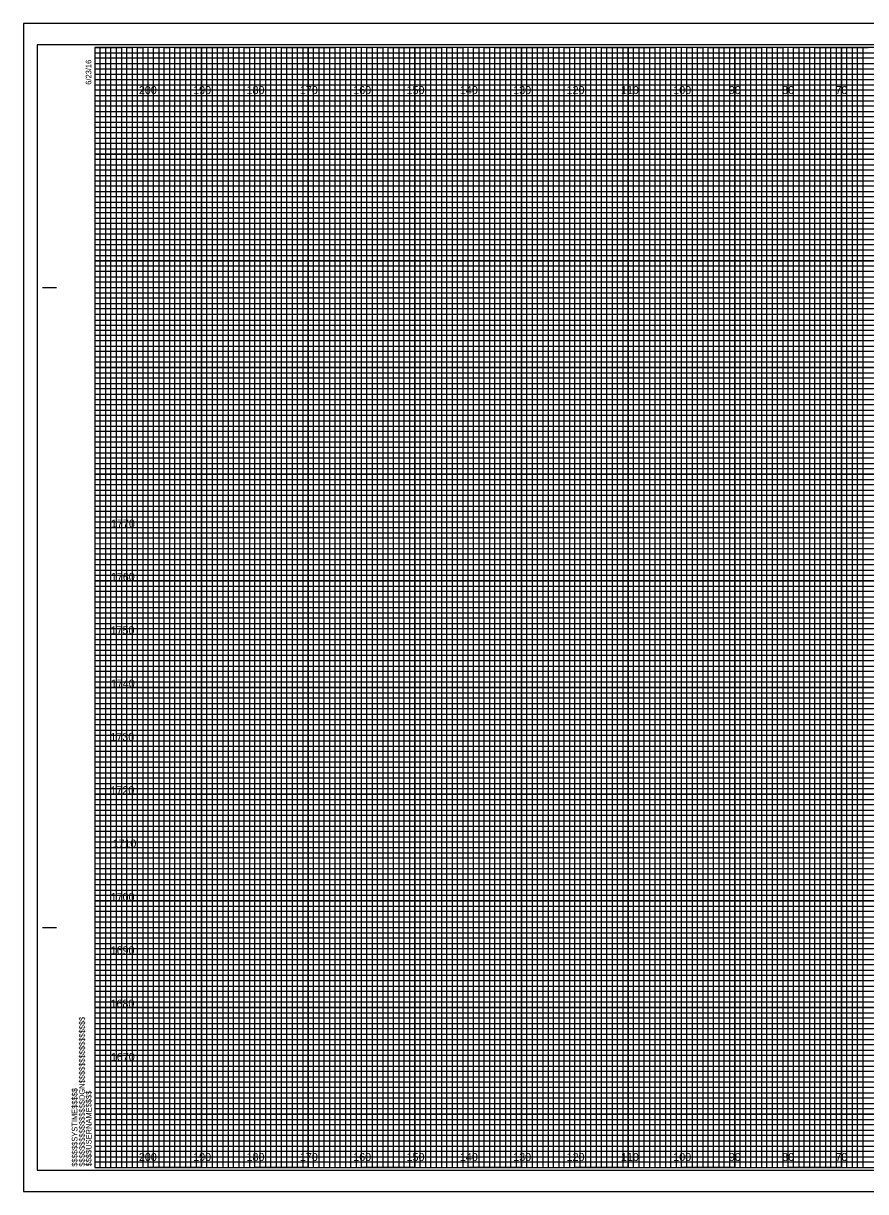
# Model space of a CAD drawing. Extents: x -419 to 4739, y -630 to 13534.
# Drawn here: x 2640.9 to 2798.8, y 194.1 to 413.1 of the extents above; entities that cross this region are included whole.
import ezdxf

# ---------------------------------------------------------------- set-up
doc = ezdxf.new("R2010")
doc.units = 0
for name, color, linetype in [('Old_Level_62', 7, 'Continuous'), ('Pattern 1', 7, 'Continuous'), ('Pattern 18', 7, 'Continuous'), ('Pattern 4', 7, 'Continuous'), ('Pattern 5', 7, 'Continuous'), ('Prop Dimension', 7, 'Continuous'), ('Prop Horizontal Alignment', 7, 'Continuous'), ('Raster_Level_0', 7, 'Continuous'), ('Scratch_Level_0', 7, 'Continuous'), ('Scratch_Level_3', 7, 'Continuous'), ('Scratch_Level_5', 7, 'Continuous')]:
    doc.layers.add(name, color=color, linetype=linetype)

msp = doc.modelspace()

# ---------------------------------------------------------------- linework, layer by layer
at = {"layer": 'Old_Level_62'}
for p, q in [((2644.45, 363.59), (2646.95, 363.59)), ((2644.55, 363.59), (2647.05, 363.59)), ((2644.45, 243.59), (2646.95, 243.59)), ((2644.55, 243.59), (2647.05, 243.59)), ((2654.25, 198.59), (2654.25, 198.59)), ((2654.25, 198.59), (2654.25, 198.59)), ((2654.25, 198.59), (2654.25, 198.59)), ((2654.25, 198.59), (2654.25, 198.59)), ((2654.25, 198.59), (2654.25, 198.59)), ((2654.25, 198.59), (2654.25, 198.59)), ((2654.25, 198.59), (2654.25, 198.59))]:
    msp.add_line(p, q, dxfattribs=at)
msp.add_lwpolyline([(2974.25, 408.59), (2654.25, 408.59), (2654.25, 198.59), (2974.25, 198.59)], close=True, dxfattribs=at)
at = {"layer": 'Pattern 18'}
msp.add_lwpolyline([(2640.85, 194.09), (2977.55, 194.09), (2977.55, 413.09), (2640.85, 413.09)], close=True, dxfattribs=at)
at = {"layer": 'Pattern 4'}
for p, q in [((2654.25, 407.59), (2914.25, 407.59)), ((2914.25, 406.57), (2654.25, 406.57)), ((2654.25, 406.57), (2654.25, 405.59)), ((2654.25, 405.59), (2914.25, 405.59)), ((2914.25, 404.48), (2654.25, 404.48)), ((2654.25, 404.48), (2654.25, 402.59)), ((2654.25, 402.59), (2974.25, 402.59))]:
    msp.add_line(p, q, dxfattribs=at)
for points in [[(2654.25, 401.59), (2924.25, 401.59), (2974.25, 401.59), (2974.25, 400.59), (2654.25, 400.59)], [(2654.25, 399.59), (2974.25, 399.59), (2974.25, 397.59), (2654.25, 397.59)], [(2654.25, 396.59), (2974.25, 396.59), (2974.25, 395.59), (2654.25, 395.57)], [(2654.25, 394.59), (2974.25, 394.59), (2974.25, 392.59), (2654.25, 392.59)], [(2654.25, 391.59), (2974.25, 391.59), (2974.25, 390.59), (2654.25, 390.59)], [(2654.25, 389.59), (2974.25, 389.59), (2974.25, 387.59), (2654.25, 387.59)], [(2654.25, 386.59), (2974.25, 386.59), (2974.25, 385.59), (2654.25, 385.59)], [(2654.25, 384.59), (2974.25, 384.59), (2974.25, 382.59), (2654.25, 382.59)], [(2654.25, 381.59), (2974.25, 381.59), (2974.25, 380.59), (2654.25, 380.59)], [(2654.25, 379.59), (2974.25, 379.59), (2974.25, 377.59), (2654.25, 377.59)], [(2654.25, 376.59), (2974.25, 376.59), (2974.25, 375.59), (2654.25, 375.59)], [(2654.25, 374.59), (2974.25, 374.59), (2974.25, 372.54), (2974.25, 371.59), (2974.25, 370.59), (2654.25, 370.59)], [(2654.25, 372.59), (2974.25, 372.59), (2974.25, 371.59), (2654.25, 371.59)], [(2654.25, 369.59), (2974.25, 369.59), (2974.25, 367.59), (2654.25, 367.62)], [(2654.25, 367.62), (2974.25, 367.59), (2974.25, 366.59), (2654.25, 366.59)], [(2654.25, 365.59), (2974.25, 365.59), (2974.25, 364.59), (2654.25, 364.59)], [(2654.25, 362.59), (2974.25, 362.59), (2974.25, 361.59), (2654.25, 361.59)], [(2654.25, 360.59), (2974.25, 360.59), (2974.25, 359.59), (2654.25, 359.59)], [(2654.18, 357.48), (2974.25, 357.48), (2974.25, 356.47), (2654.18, 356.47)], [(2654.25, 355.59), (2974.25, 355.59), (2974.25, 354.59), (2654.25, 354.59)], [(2654.25, 352.59), (2974.25, 352.59), (2974.25, 351.59), (2654.25, 351.59)], [(2654.25, 350.59), (2974.25, 350.59), (2974.25, 349.59), (2654.25, 349.59)], [(2654.25, 347.59), (2974.25, 347.59), (2974.25, 346.59), (2654.25, 346.59)], [(2654.25, 345.59), (2974.25, 345.59), (2974.25, 344.59), (2654.25, 344.59)], [(2654.25, 342.59), (2974.25, 342.59), (2974.25, 341.59), (2654.25, 341.59)], [(2654.25, 340.59), (2974.25, 340.59), (2974.25, 339.59), (2654.25, 339.59)], [(2654.25, 337.59), (2974.25, 337.59), (2974.24, 336.57), (2654.25, 336.59)], [(2654.25, 335.59), (2974.25, 335.59), (2974.25, 334.59), (2654.25, 334.59)], [(2654.25, 332.59), (2974.25, 332.59), (2974.25, 331.59), (2654.25, 331.59)], [(2654.25, 330.59), (2974.25, 330.59), (2974.25, 329.59), (2654.25, 329.59)], [(2654.25, 327.59), (2974.25, 327.59), (2974.25, 326.59), (2654.25, 326.59)], [(2654.25, 325.59), (2974.25, 325.59), (2974.25, 324.59), (2654.25, 324.59)], [(2654.25, 322.59), (2974.25, 322.59), (2974.25, 321.59), (2654.25, 321.59)], [(2654.25, 320.59), (2974.25, 320.59), (2974.25, 319.59), (2654.25, 319.59)], [(2654.25, 317.59), (2974.25, 317.59), (2974.25, 316.59), (2654.25, 316.59)], [(2654.25, 315.58), (2974.32, 315.5), (2974.25, 314.59), (2654.25, 314.59)], [(2654.25, 312.59), (2974.25, 312.59), (2974.25, 311.59), (2654.25, 311.59)], [(2654.25, 310.59), (2974.25, 310.59), (2974.25, 309.59), (2654.25, 309.59)], [(2654.25, 307.59), (2974.25, 307.59), (2974.25, 306.59), (2654.25, 306.59)], [(2654.25, 305.59), (2974.25, 305.59), (2974.25, 304.59), (2654.25, 304.59)], [(2654.25, 302.59), (2974.25, 302.59), (2974.25, 301.59), (2654.25, 301.59)], [(2654.25, 300.59), (2974.25, 300.59), (2974.25, 299.59), (2654.25, 299.59)], [(2654.25, 297.59), (2974.25, 297.59), (2974.25, 296.59), (2654.25, 296.59)], [(2654.25, 295.59), (2974.25, 295.59), (2974.25, 294.59), (2654.25, 294.59)], [(2654.25, 292.59), (2974.25, 292.59), (2974.25, 291.59), (2654.25, 291.59)], [(2654.25, 290.59), (2974.25, 290.59), (2974.25, 289.59), (2654.25, 289.59)], [(2654.25, 287.59), (2974.25, 287.59), (2974.25, 286.59), (2654.25, 286.59)], [(2654.25, 285.59), (2974.25, 285.59), (2974.25, 284.59), (2654.25, 284.59)], [(2654.25, 282.59), (2974.25, 282.59), (2974.25, 281.59), (2654.25, 281.59)], [(2654.25, 280.59), (2974.25, 280.59), (2974.25, 279.59), (2654.25, 279.59)], [(2654.25, 277.59), (2974.25, 277.59), (2974.24, 276.57), (2654.25, 276.59)], [(2654.25, 275.59), (2974.25, 275.59), (2974.25, 274.59), (2654.25, 274.59)], [(2654.25, 272.59), (2974.25, 272.59), (2974.25, 271.59), (2654.25, 271.59)], [(2654.25, 270.59), (2974.25, 270.59), (2974.25, 269.59), (2654.25, 269.59)], [(2654.25, 267.59), (2974.25, 267.59), (2974.25, 266.59), (2654.25, 266.59)], [(2654.25, 265.59), (2974.25, 265.59), (2974.25, 264.59), (2654.25, 264.59)], [(2654.25, 262.59), (2974.25, 262.59), (2974.25, 261.59), (2654.25, 261.59)], [(2654.25, 260.59), (2974.25, 260.59), (2974.25, 259.59), (2654.25, 259.59)], [(2654.25, 257.59), (2974.25, 257.59), (2974.25, 256.59), (2654.25, 256.59)], [(2654.25, 255.58), (2974.32, 255.5), (2974.25, 254.59), (2654.25, 254.59)], [(2654.25, 252.59), (2974.25, 252.59), (2974.25, 251.59), (2654.25, 251.59)], [(2654.25, 250.59), (2974.25, 250.59), (2974.25, 249.59), (2654.25, 249.59)], [(2654.25, 247.59), (2974.25, 247.59), (2974.25, 246.59), (2654.25, 246.59)], [(2654.25, 245.59), (2974.25, 245.59), (2974.25, 244.59), (2654.25, 244.59)], [(2654.25, 242.59), (2974.25, 242.59), (2974.25, 241.59), (2654.25, 241.59)], [(2654.25, 240.59), (2974.25, 240.59), (2974.25, 239.59), (2654.25, 239.59)], [(2654.25, 237.59), (2974.25, 237.59), (2974.25, 236.59), (2654.25, 236.59)], [(2654.25, 235.59), (2974.25, 235.59), (2974.25, 234.59), (2654.25, 234.59)], [(2654.25, 232.59), (2974.25, 232.59), (2974.25, 231.59), (2654.25, 231.59)], [(2654.25, 230.59), (2974.25, 230.59), (2974.25, 229.59), (2654.25, 229.59)], [(2654.25, 227.59), (2974.25, 227.59), (2974.25, 226.59), (2654.25, 226.59)], [(2654.25, 225.59), (2974.25, 225.59), (2974.25, 224.59), (2654.25, 224.59)], [(2654.25, 222.59), (2974.25, 222.59), (2974.25, 221.59), (2654.25, 221.59)], [(2654.25, 220.59), (2974.25, 220.59), (2974.25, 219.59), (2654.25, 219.59)], [(2654.25, 217.59), (2974.25, 217.59), (2974.25, 216.59), (2654.25, 216.59)], [(2654.25, 215.59), (2974.25, 215.59), (2974.25, 214.59), (2654.25, 214.59)], [(2654.25, 212.59), (2974.25, 212.59), (2974.25, 211.59), (2654.25, 211.59)], [(2654.25, 210.59), (2974.25, 210.59), (2974.25, 209.59), (2654.25, 209.59)], [(2654.25, 207.59), (2974.25, 207.59), (2974.25, 206.59), (2654.25, 206.59)], [(2654.25, 205.59), (2974.25, 205.59), (2974.25, 204.59), (2654.25, 204.59)], [(2654.25, 202.59), (2974.25, 202.59), (2974.25, 201.59), (2654.25, 201.59)], [(2654.25, 200.59), (2974.25, 200.59), (2974.25, 199.59), (2654.25, 199.59)]]:
    msp.add_lwpolyline(points, dxfattribs=at)
at = {"layer": 'Pattern 5'}
for p, q in [((2977.55, 413.09), (2640.85, 413.09)), ((2640.85, 413.09), (2640.85, 194.09)), ((2640.85, 194.09), (2977.55, 194.09))]:
    msp.add_line(p, q, dxfattribs=at)
at = {"layer": 'Prop Dimension'}
for points in [[(2654.25, 198.59), (2655.25, 198.59), (2655.25, 408.59), (2656.25, 408.59), (2656.25, 198.59)], [(2656.25, 198.59), (2657.25, 198.59), (2657.25, 408.59), (2658.25, 408.59), (2658.25, 198.59)], [(2659.25, 198.59), (2660.25, 198.59), (2660.25, 408.59), (2661.25, 408.59), (2661.25, 198.59)], [(2661.25, 198.59), (2662.25, 198.59), (2662.25, 408.59), (2663.25, 408.59), (2663.25, 198.59)], [(2664.25, 198.59), (2665.25, 198.59), (2665.25, 408.59), (2666.25, 408.59), (2666.25, 198.59)], [(2666.25, 198.59), (2667.25, 198.59), (2667.25, 408.59), (2668.25, 408.59), (2668.25, 198.59)], [(2669.25, 198.59), (2670.25, 198.59), (2670.25, 408.59), (2671.25, 408.59), (2671.25, 198.59)], [(2671.25, 198.59), (2672.25, 198.59), (2672.25, 408.59), (2673.25, 408.59), (2673.25, 198.59)], [(2674.25, 198.59), (2675.25, 198.59), (2675.25, 408.59), (2676.25, 408.59), (2676.25, 198.59)], [(2676.25, 198.59), (2677.25, 198.59), (2677.25, 408.59), (2678.25, 408.59), (2678.25, 198.59)], [(2679.25, 198.59), (2680.25, 198.59), (2680.25, 408.59), (2681.25, 408.59), (2681.25, 198.59)], [(2681.25, 198.59), (2682.25, 198.59), (2682.25, 408.59), (2683.25, 408.59), (2683.25, 198.59)], [(2684.25, 198.59), (2685.25, 198.59), (2685.25, 408.59), (2686.25, 408.59), (2686.25, 198.59)], [(2686.25, 198.59), (2687.25, 198.59), (2687.25, 408.59), (2688.25, 408.59), (2688.25, 198.59)], [(2689.25, 198.59), (2690.25, 198.59), (2690.25, 408.59), (2691.25, 408.59), (2691.25, 198.59)], [(2691.25, 198.59), (2692.25, 198.59), (2692.25, 408.59), (2693.25, 408.59), (2693.25, 198.59)], [(2694.25, 198.59), (2695.25, 198.59), (2695.25, 408.59), (2696.25, 408.59), (2696.25, 198.59)], [(2696.25, 198.59), (2697.25, 198.59), (2697.25, 408.59), (2698.25, 408.59), (2698.25, 198.59)], [(2699.25, 198.59), (2700.25, 198.59), (2700.25, 408.59), (2701.25, 408.59), (2701.25, 198.59)], [(2701.25, 198.59), (2702.25, 198.59), (2702.25, 408.59), (2703.25, 408.59), (2703.25, 198.59)], [(2704.25, 198.59), (2705.25, 198.59), (2705.25, 408.59), (2706.25, 408.59), (2706.25, 198.59)], [(2706.25, 198.59), (2707.25, 198.59), (2707.25, 408.59), (2708.25, 408.59), (2708.25, 198.59)], [(2709.25, 198.59), (2710.25, 198.59), (2710.25, 408.59), (2711.25, 408.59), (2711.25, 198.59)], [(2711.25, 198.59), (2712.25, 198.59), (2712.25, 408.59), (2713.25, 408.59), (2713.25, 198.59)], [(2714.25, 198.59), (2715.25, 198.59), (2715.25, 408.59), (2716.25, 408.59), (2716.25, 198.59)], [(2716.25, 198.59), (2717.25, 198.59), (2717.25, 408.59), (2718.25, 408.59), (2718.25, 198.59)], [(2719.25, 198.59), (2720.25, 198.59), (2720.25, 408.59), (2721.25, 408.59), (2721.25, 198.59)], [(2721.25, 198.59), (2722.25, 198.59), (2722.25, 408.59), (2723.25, 408.59), (2723.25, 198.59)], [(2724.25, 198.59), (2725.25, 198.59), (2725.25, 408.59), (2726.25, 408.59), (2726.25, 198.59)], [(2726.25, 198.59), (2727.25, 198.59), (2727.25, 408.59), (2728.25, 408.59), (2728.25, 198.59)], [(2729.25, 198.59), (2730.25, 198.59), (2730.25, 408.59), (2731.25, 408.59), (2731.25, 198.59)], [(2731.25, 198.59), (2732.25, 198.59), (2732.25, 408.59), (2733.25, 408.59), (2733.25, 198.59)], [(2734.25, 198.59), (2735.25, 198.59), (2735.25, 408.59), (2736.25, 408.59), (2736.25, 198.59)], [(2736.25, 198.59), (2737.25, 198.59), (2737.25, 408.59), (2738.25, 408.59), (2738.25, 198.59)], [(2739.25, 198.59), (2740.25, 198.59), (2740.25, 408.59), (2741.25, 408.59), (2741.25, 198.59)], [(2741.25, 198.59), (2742.25, 198.59), (2742.25, 408.59), (2743.25, 408.59), (2743.25, 198.59)], [(2744.25, 198.59), (2745.25, 198.59), (2745.25, 408.59), (2746.25, 408.59), (2746.25, 198.59)], [(2746.25, 198.59), (2747.25, 198.59), (2747.25, 408.59), (2748.25, 408.59), (2748.25, 198.59)], [(2749.25, 198.59), (2750.25, 198.59), (2750.25, 408.59), (2751.25, 408.59), (2751.25, 198.59)], [(2751.25, 198.59), (2752.25, 198.59), (2752.25, 408.59), (2753.25, 408.59), (2753.25, 198.59)], [(2754.25, 198.59), (2755.25, 198.59), (2755.25, 408.59), (2756.25, 408.59), (2756.25, 198.59)], [(2756.25, 198.59), (2757.25, 198.59), (2757.25, 408.59), (2758.25, 408.59), (2758.25, 198.59)], [(2759.25, 198.59), (2760.25, 198.59), (2760.25, 408.59), (2761.25, 408.59), (2761.25, 198.59)], [(2761.25, 198.59), (2762.25, 198.59), (2762.25, 408.59), (2763.25, 408.59), (2763.25, 198.59)], [(2764.25, 198.59), (2765.25, 198.59), (2765.25, 408.59), (2766.25, 408.59), (2766.25, 198.59)], [(2766.25, 198.59), (2767.25, 198.59), (2767.25, 408.59), (2768.25, 408.59), (2768.25, 198.59)], [(2769.25, 198.59), (2770.25, 198.59), (2770.25, 408.59), (2771.25, 408.59), (2771.25, 198.59)], [(2771.25, 198.59), (2772.25, 198.59), (2772.25, 408.59), (2773.25, 408.59), (2773.25, 198.59)], [(2774.25, 198.59), (2775.25, 198.59), (2775.25, 408.59), (2776.25, 408.59), (2776.25, 198.59)], [(2776.25, 198.59), (2777.25, 198.59), (2777.25, 408.59), (2778.25, 408.59), (2778.25, 198.59)], [(2779.25, 198.59), (2780.25, 198.59), (2780.25, 408.59), (2781.25, 408.59), (2781.25, 198.59)], [(2781.25, 198.59), (2782.25, 198.59), (2782.25, 408.59), (2783.25, 408.59), (2783.25, 198.59)], [(2784.25, 198.59), (2785.25, 198.59), (2785.25, 408.59), (2786.25, 408.59), (2786.25, 198.59)], [(2786.25, 198.59), (2787.25, 198.59), (2787.25, 408.59), (2788.25, 408.59), (2788.25, 198.59)], [(2789.25, 198.59), (2790.25, 198.59), (2790.25, 408.59), (2791.25, 408.59), (2791.25, 198.59)], [(2791.25, 198.59), (2792.25, 198.59), (2792.25, 408.59), (2793.25, 408.59), (2793.25, 198.59)], [(2794.25, 198.59), (2795.25, 198.59), (2795.25, 408.59), (2796.25, 408.59), (2796.25, 198.59)], [(2796.25, 198.59), (2797.25, 198.59), (2797.25, 408.59), (2798.25, 408.59), (2798.25, 198.59)]]:
    msp.add_lwpolyline(points, dxfattribs=at)
at = {"layer": 'Prop Horizontal Alignment'}
for points in [[(2654.25, 408.59), (2659.25, 408.59), (2659.25, 198.59), (2669.25, 198.59), (2669.25, 408.59), (2679.25, 408.59), (2679.25, 198.59), (2689.25, 198.59), (2689.25, 408.59), (2699.25, 408.59), (2699.25, 198.59), (2709.25, 198.59), (2709.25, 408.59), (2719.25, 408.59), (2719.25, 198.59), (2729.25, 198.59), (2729.25, 408.59), (2739.25, 408.59), (2739.25, 198.59), (2749.25, 198.59), (2749.25, 408.59), (2759.25, 408.59), (2759.25, 198.59), (2769.25, 198.59), (2769.25, 408.59), (2779.25, 408.59), (2779.25, 198.59), (2789.25, 198.59), (2789.25, 408.59), (2799.25, 408.59)], [(2654.25, 403.59), (2929.25, 403.59)], [(2654.25, 383.59), (2974.25, 383.59), (2974.25, 393.59), (2654.25, 393.59)], [(2654.25, 363.59), (2974.25, 363.59), (2974.25, 373.59), (2654.25, 373.59)], [(2654.25, 343.59), (2974.25, 343.59), (2974.25, 353.59), (2654.25, 353.59)], [(2654.25, 323.59), (2974.25, 323.59), (2974.25, 333.59), (2654.25, 333.59)], [(2654.25, 303.59), (2974.25, 303.59), (2974.25, 313.59), (2654.25, 313.59)], [(2654.25, 283.59), (2974.25, 283.59), (2974.25, 293.59), (2654.25, 293.59)], [(2654.25, 263.59), (2974.25, 263.59), (2974.25, 273.59), (2654.25, 273.59)], [(2654.25, 243.59), (2974.25, 243.59), (2974.25, 253.59), (2654.25, 253.59)], [(2654.25, 223.59), (2974.25, 223.59), (2974.25, 233.59), (2654.25, 233.59)], [(2654.25, 203.59), (2974.25, 203.59), (2974.25, 213.59), (2654.25, 213.59)]]:
    msp.add_lwpolyline(points, dxfattribs=at)
at = {"layer": 'Scratch_Level_0'}
for p, q in [((2664.25, 198.59), (2664.25, 408.59)), ((2674.25, 198.59), (2674.25, 408.59)), ((2684.25, 198.59), (2684.25, 408.59)), ((2694.25, 198.59), (2694.25, 408.59)), ((2704.25, 198.59), (2704.25, 408.59)), ((2714.25, 198.59), (2714.25, 408.59)), ((2724.25, 198.59), (2724.25, 408.59)), ((2734.25, 198.59), (2734.25, 408.59)), ((2744.25, 198.59), (2744.25, 408.59)), ((2754.25, 198.59), (2754.25, 408.59)), ((2764.25, 198.59), (2764.25, 408.59)), ((2774.25, 198.59), (2774.25, 408.59)), ((2784.25, 198.59), (2784.25, 408.59)), ((2794.25, 198.59), (2794.25, 408.59)), ((2654.25, 398.59), (2974.25, 398.59)), ((2654.25, 388.59), (2974.25, 388.59)), ((2654.25, 378.59), (2974.25, 378.59)), ((2654.25, 368.59), (2974.25, 368.59)), ((2654.25, 358.59), (2974.25, 358.59)), ((2654.25, 348.59), (2974.25, 348.59)), ((2654.25, 338.59), (2974.25, 338.59)), ((2654.25, 328.59), (2974.25, 328.59)), ((2654.25, 318.59), (2974.25, 318.59)), ((2654.25, 308.59), (2974.25, 308.59)), ((2654.25, 298.59), (2974.25, 298.59)), ((2654.25, 288.59), (2974.25, 288.59)), ((2654.25, 278.59), (2974.25, 278.59)), ((2654.25, 268.59), (2974.25, 268.59)), ((2654.25, 258.59), (2974.25, 258.59)), ((2654.25, 248.59), (2974.25, 248.59)), ((2654.25, 238.59), (2974.25, 238.59)), ((2654.25, 228.59), (2974.25, 228.59)), ((2654.25, 218.59), (2974.25, 218.59)), ((2654.25, 208.59), (2974.25, 208.59))]:
    msp.add_line(p, q, dxfattribs=at)
at = {"layer": 'Scratch_Level_3'}
for p, q in [((2664.25, 408.59), (2654.25, 408.59)), ((2664.25, 198.59), (2664.25, 408.59)), ((2684.25, 408.59), (2674.25, 408.59)), ((2674.25, 408.59), (2674.25, 198.59)), ((2684.25, 198.59), (2684.25, 408.59)), ((2704.25, 408.59), (2694.25, 408.59)), ((2694.25, 408.59), (2694.25, 198.59)), ((2704.25, 198.59), (2704.25, 408.59)), ((2724.25, 408.59), (2714.25, 408.59)), ((2714.25, 408.59), (2714.25, 198.59)), ((2724.25, 198.59), (2724.25, 408.59)), ((2744.25, 408.59), (2734.25, 408.59)), ((2734.25, 408.59), (2734.25, 198.59)), ((2744.25, 198.59), (2744.25, 408.59)), ((2764.25, 408.59), (2754.25, 408.59)), ((2754.25, 408.59), (2754.25, 198.59)), ((2764.25, 198.59), (2764.25, 408.59)), ((2784.25, 408.59), (2774.25, 408.59)), ((2774.25, 408.59), (2774.25, 198.59)), ((2784.25, 198.59), (2784.25, 408.59)), ((2804.25, 408.59), (2794.25, 408.59)), ((2794.25, 408.59), (2794.25, 198.59)), ((2674.25, 198.59), (2664.25, 198.59)), ((2694.25, 198.59), (2684.25, 198.59)), ((2714.25, 198.59), (2704.25, 198.59)), ((2734.25, 198.59), (2724.25, 198.59)), ((2754.25, 198.59), (2744.25, 198.59)), ((2774.25, 198.59), (2764.25, 198.59)), ((2794.25, 198.59), (2784.25, 198.59))]:
    msp.add_line(p, q, dxfattribs=at)
for points in [[(2654.25, 398.59), (2974.25, 398.59), (2974.25, 388.59), (2654.25, 388.59)], [(2654.25, 378.59), (2974.25, 378.59), (2974.25, 368.59), (2654.25, 368.59)], [(2654.25, 358.59), (2974.25, 358.59), (2974.25, 348.59), (2654.25, 348.59)], [(2654.25, 338.59), (2974.25, 338.59), (2974.25, 328.59), (2654.25, 328.59)], [(2654.25, 318.59), (2974.25, 318.59), (2974.25, 308.59), (2654.25, 308.59)], [(2654.25, 298.59), (2974.25, 298.59), (2974.25, 288.59), (2654.25, 288.59)], [(2654.25, 278.59), (2974.25, 278.59), (2974.25, 268.59), (2654.25, 268.59)], [(2654.25, 258.59), (2974.25, 258.59), (2974.25, 248.59), (2654.25, 248.59)], [(2654.25, 238.59), (2974.25, 238.59), (2974.25, 228.59), (2654.25, 228.59)], [(2654.25, 218.59), (2974.25, 218.59), (2974.25, 208.59), (2654.25, 208.59)]]:
    msp.add_lwpolyline(points, dxfattribs=at)
at = {"layer": 'Scratch_Level_5'}
msp.add_lwpolyline([(2643.45, 198.09), (2976.65, 198.09), (2976.65, 409.09), (2643.45, 409.09)], close=True, dxfattribs=at)

# ---------------------------------------------------------------- texts
at = {"layer": 'Old_Level_62'}
for s, p in [('6/23/16', (2653.6, 401.59)), ('$$$$$$$$$$$$$$$$DGN$$$$$$$$$$$$$$$$', (2652.37, 198.77)), ('$$$$$$SYSTIME$$$$$', (2650.99, 198.77)), ('$$$$USERNAME$$$$', (2653.63, 198.82))]:
    msp.add_text(s, height=1.05, rotation=90, dxfattribs=at).set_placement(p)
at = {"layer": 'Pattern 1'}
for s, p in [('1770', (2657.29, 318.59)), ('1760', (2657.26, 308.59)), ('1750', (2657.21, 298.59)), ('1740', (2657.26, 288.59)), ('1730', (2657.18, 278.59)), ('1720', (2657.19, 268.59)), ('1710', (2657.57, 258.59)), ('1700', (2657.23, 248.59)), ('1690', (2657.22, 238.59)), ('1680', (2657.2, 228.59)), ('1670', (2657.26, 218.59))]:
    msp.add_text(s, height=1.5, dxfattribs=at).set_placement(p)
at = {"layer": 'Raster_Level_0'}
for s, p in [('200', (2662.52, 399.84)), ('190', (2672.7, 399.84)), ('180', (2682.7, 399.84)), ('170', (2692.7, 399.84)), ('160', (2702.7, 399.84)), ('150', (2712.7, 399.84)), ('140', (2722.7, 399.84)), ('130', (2732.7, 399.84)), ('120', (2742.7, 399.84)), ('110', (2752.88, 399.84)), ('100', (2762.7, 399.84)), ('90', (2773.11, 399.84)), ('80', (2783.11, 399.84)), ('70', (2793.11, 399.84)), ('200', (2662.52, 199.84)), ('190', (2672.7, 199.84)), ('180', (2682.7, 199.84)), ('170', (2692.7, 199.84)), ('160', (2702.7, 199.84)), ('150', (2712.7, 199.84)), ('140', (2722.7, 199.84)), ('130', (2732.7, 199.84)), ('120', (2742.7, 199.84)), ('110', (2752.88, 199.84)), ('100', (2762.7, 199.84)), ('90', (2773.11, 199.84)), ('80', (2783.11, 199.84)), ('70', (2793.11, 199.84))]:
    msp.add_text(s, height=1.5, dxfattribs=at).set_placement(p)

doc.saveas('drawing.dxf')
